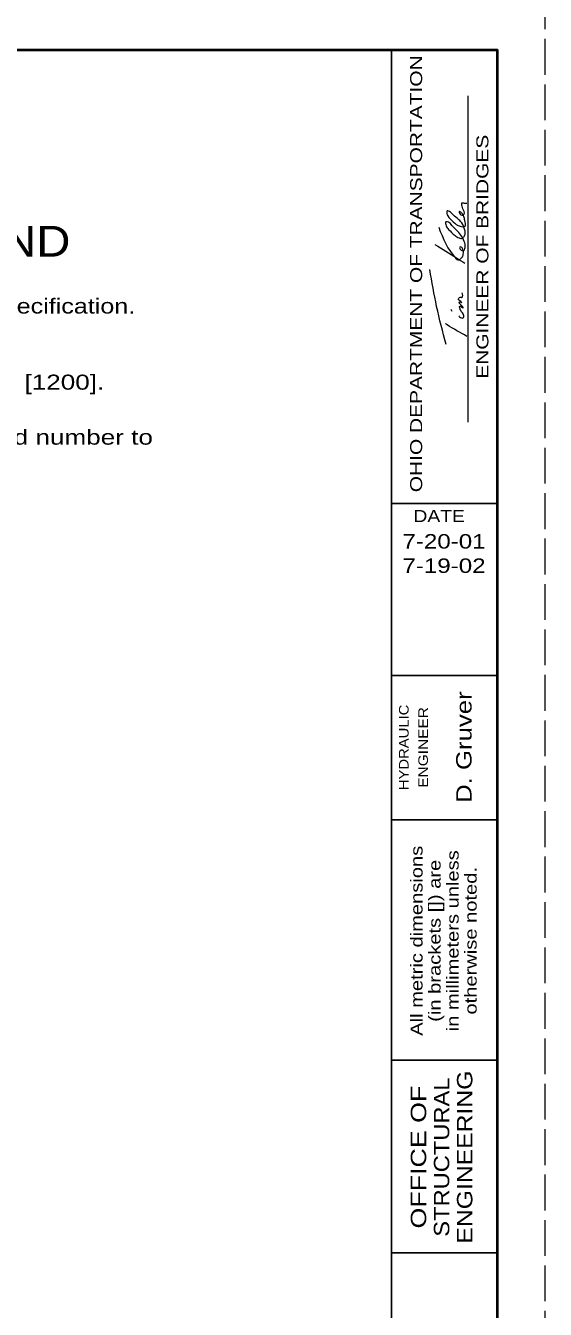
# Model space of a CAD drawing. Extents: x 1170.6 to 1204.6, y 975 to 1019.
# Drawn here: x 1199.19 to 1204.59, y 983.44 to 996.78 of the extents above; entities that cross this region are included whole.
import ezdxf
from ezdxf.enums import TextEntityAlignment as Align

# ---------------------------------------------------------------- set-up
doc = ezdxf.new("R2010")
doc.units = 0
doc.header["$LTSCALE"] = 0.062
doc.linetypes.add('LONG_DASHED', pattern=[7.5, 6, -1.5])
doc.layers.add('1', color=7, linetype='Continuous', lineweight=13)

msp = doc.modelspace()

# ---------------------------------------------------------------- linework, layer by layer
at = {"layer": '1', "lineweight": 25}
for p, q in [((1172.59275, 996.52625), (1204.09275, 996.52625)), ((1202.99275, 975.52625), (1202.99275, 996.52625)), ((1204.09275, 996.52625), (1204.09275, 975.52625)), ((1204.09275, 991.81042), (1202.99275, 991.81042)), ((1204.09275, 990.02625), (1202.99275, 990.02625)), ((1204.09275, 988.52625), (1202.99275, 988.52625)), ((1204.09275, 986.02625), (1202.99275, 986.02625)), ((1204.09275, 984.02625), (1202.99275, 984.02625))]:
    msp.add_line(p, q, dxfattribs=at)
at = {"layer": '1'}
for p, q in [((1203.7915, 992.65725), (1203.7915, 996.04733)), ((1203.624, 993.80817), (1203.61383, 993.82742))]:
    msp.add_line(p, q, dxfattribs=at)
at = {"layer": '1', "linetype": 'LONG_DASHED'}
msp.add_lwpolyline([(1170.59275, 975.02625), (1204.59275, 975.02625), (1204.59275, 997.02625), (1170.59275, 997.02625)], close=True, dxfattribs=at)
at = {"layer": '1', "lineweight": 40}
msp.add_lwpolyline([(1172.59275, 996.52625), (1204.09275, 996.52625), (1204.09275, 975.52625), (1172.59275, 975.52625)], close=True, dxfattribs=at)
at = {"layer": '1'}
for points in [[(1203.48458, 994.68325), (1203.66775, 994.35492), (1203.68292, 994.34433), (1203.69308, 994.34433), (1203.725, 994.368), (1203.74008, 994.40217), (1203.73508, 994.45342), (1203.71817, 994.47525), (1203.70467, 994.47525), (1203.70292, 994.46225), (1203.71308, 994.44708), (1203.72658, 994.43867), (1203.74167, 994.43867), (1203.75683, 994.46025), (1203.76025, 994.47958), (1203.75, 994.53492), (1203.66775, 994.65533), (1203.62225, 994.7), (1203.58533, 994.73458), (1203.56017, 994.73675), (1203.56192, 994.69817), (1203.58708, 994.65942), (1203.65433, 994.59708), (1203.69642, 994.57167), (1203.73008, 994.56717), (1203.75342, 994.59317), (1203.76025, 994.62733), (1203.75517, 994.65308), (1203.725, 994.72625), (1203.69475, 994.75825), (1203.63417, 994.81167), (1203.6055, 994.8375), (1203.572, 994.85275), (1203.56858, 994.82475), (1203.57867, 994.79892), (1203.63583, 994.739), (1203.7065, 994.69175), (1203.7585, 994.69408), (1203.75683, 994.75175), (1203.745, 994.79467), (1203.73167, 994.82042), (1203.7215, 994.83117), (1203.69808, 994.84617), (1203.69983, 994.82908), (1203.73508, 994.80758), (1203.75, 994.81833), (1203.73692, 994.872), (1203.72833, 994.89992), (1203.725, 994.91258), (1203.725, 994.92542), (1203.725, 994.93408), (1203.75, 994.93192), (1203.77542, 994.93192)], [(1203.44575, 994.501), (1203.6695, 994.3635), (1203.75517, 994.30783)], [(1203.562, 993.464), (1203.46333, 993.85925), (1203.39208, 994.24158)], [(1203.69308, 993.76292), (1203.70133, 993.75225), (1203.7385, 993.73933), (1203.74325, 993.77175), (1203.71817, 993.80817), (1203.70292, 993.84442), (1203.70292, 993.86367), (1203.71817, 993.85742), (1203.72833, 993.84658), (1203.7385, 993.84225), (1203.71483, 993.87442), (1203.70292, 993.88942), (1203.69983, 993.90675), (1203.72325, 993.90017), (1203.71483, 993.90883), (1203.68967, 993.93667), (1203.69983, 993.95183), (1203.71658, 993.95383), (1203.725, 993.95183), (1203.73508, 993.97317), (1203.72833, 994.00108)], [(1203.77717, 993.54842), (1203.572, 993.66842), (1203.55642, 993.67883)]]:
    msp.add_spline(points, degree=3, dxfattribs=at)

# ---------------------------------------------------------------- texts
for s, height, width, p in [('OHIO DEPARTMENT OF TRANSPORTATION', 0.125, 1.3, (1203.31267, 994.1985)), ('ENGINEER OF BRIDGES', 0.125, 1.3, (1204.001, 994.37529)), ('D. Gruver', 0.16, 1.25, (1203.82617, 989.28042)), ('HYDRAULIC', 0.1, 1.15, (1203.17183, 989.27733)), ('ENGINEER', 0.1, 1.2, (1203.37275, 989.27738)), ('All metric dimensions', 0.125, 1.25, (1203.31658, 987.26833)), ('in millimeters unless', 0.125, 1.25, (1203.69158, 987.26837)), ('(in brackets []) are', 0.125, 1.25, (1203.50408, 987.26833)), ('otherwise noted.', 0.125, 1.25, (1203.87908, 987.26833)), ('ENGINEERING', 0.16, 1.2, (1203.8345, 985.02079)), ('OFFICE OF', 0.16, 1.3, (1203.3545, 985.02071)), ('STRUCTURAL', 0.16, 1.15, (1203.5945, 985.02071))]:
    msp.add_text(s, height=height, rotation=90, dxfattribs=dict(at, width=width)).set_placement(p, align=Align.CENTER)
for s, height, width, p in [('LEGEND', 0.32, 1.15, (1197.63375, 994.37642)), ('If required by conduit specification.', 0.156, 1.25, (1196.31558, 993.78533)), ('On all sizes except 48" [1200].', 0.156, 1.3, (1196.35492, 992.99442)), ('One-half of the required number to', 0.156, 1.3, (1196.354, 992.42292))]:
    msp.add_text(s, height=height, dxfattribs=dict(at, width=width)).set_placement(p)
for s, height, width, p in [('DATE', 0.125, 1.2, (1203.48946, 991.619)), ('7-20-01', 0.15, 1.25, (1203.53979, 991.3435)), ('7-19-02', 0.15, 1.25, (1203.53979, 991.09042))]:
    msp.add_text(s, height=height, dxfattribs=dict(at, width=width)).set_placement(p, align=Align.CENTER)

doc.saveas('drawing.dxf')
